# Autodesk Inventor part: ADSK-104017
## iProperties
Shininess: 27.0
Created: 2001-05
Part Number: ADSK-104017
Document SubType Name: Modeling
Designer: Administrator
Stock Number: ADSK-104017
Density: 1 g/cm^3
Density: 0.0
Volumn: 0.0
Area: 0.0
PropertySet Name: Model Information
Control State: 0
Master: False
Checked Out: False
Author: Administrator
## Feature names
1. Extrusion1
2. Hole1
3. Extrusion3
4. Chamfer1
